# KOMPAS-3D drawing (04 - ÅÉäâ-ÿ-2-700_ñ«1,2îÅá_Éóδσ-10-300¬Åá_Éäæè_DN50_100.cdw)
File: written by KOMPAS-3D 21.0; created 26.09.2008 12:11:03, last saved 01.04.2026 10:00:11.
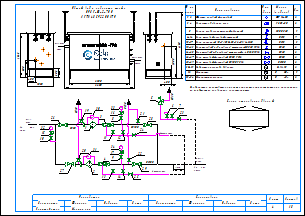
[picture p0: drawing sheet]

Sheets 1-2: A3, landscape

Document properties: Наименование: Макро:21; Автор: RaskoAdmin; Форматы листов документа: 2xA3; Полное имя файла: \\UR38nt01\Departments\КТО\КБ ПУРДГ\Заявки\Прайс-лист на типовые шкафы ГРПШ\ПРДГ_стандарт_20_03_2026\ПРДГ с РДСК\ПРДГ-Ш-2-700_до1,2МПа_Рвых-10-300кПа_РДСК_DN50_100.cdw

Title block, sheet 1: Наименование: Пункт учета газа / ПУГ-Ш-400-Р / ЛГТИ.485922.001ТУ; designation: ЛГТИ.03.4411141; sheet number: 1; Количество листов документа: 2; organisation: ООО "ЭЛЬСТЕР Газэлектроника"; Форматы листов документа: A3; stored path: C:\Рабочие документы\Компас\ПУГ\Схема.cdw; Разработал: Устинов; Проверил: Кошкин; Утвердил: Кошкин
Title block, sheet 2: sheet number: 2; stored path: D:\Рабочие документы\Заявки\ПУРДГ\ПУРДГ-ШУЭО-2-100-Р 4411220.cdw; designation, second copy: ЛГТИ.03.4411141-

Views: Вид 1, Вид 2
Referenced files: wcvoit.frw
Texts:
  Normal
  Вход
  газа
  PDI
  Выход
  Р=     кПа
  DN100
  DN50
  DN20
  Импульс DN20
  ≥5DN
  HYSWLongFangSong
  № на
  схеме
  Усл.
  обозн.
  Марка
  (модель)
  Кол.
  Фильтр газовый фланцевый
  ФГ 16-50
  Регулятор давления газа
  РДCК-50
  Клапан предохранительный сбросной
  КПС DN20
  Кран шаровой газовый латунный
  DN15
  Кран кнопочный VE-РАСКО-НЗ-1,6-G1/2-М20
  Кран шаровой "под приварку" штуцерный DN20 PN16
  Кран шаровой "под приварку" штуцерный п/п DN20 PN16
  Кран шаровой фланцевый DN50 PN16
  Кран шаровой фланцевый DN100 PN16
  Индикатор перепада давления
  Delta 15
  Манометр
  Манометр-напоромер
  0...     МПа
  0...     кПа
  Общий вид и габариты шкафа
  ПРДГ-Ш-2-700
  Выход газа
  Вход газа
  Схема открывания дверей
  Р=        МПа
  logo-rasko-ge.png
  Предприятие изготовитель может заменять комплектующие на аналогичные,
  не ухудшающие заявленных характеристик.
  Должность
  Конструктор
  Фамилия
  Подпись
  Дата
  Согласовано
  Максимкин
  Лист
  Листов
  POLYLINE_STYLE_0.18_RGB_0_0_0
  POLYLINE_STYLE_0.50_RGB_0_0_0
  POLYLINE_STYLE_0.34_RGB_0_0_0
  PHANTOM_RGB_0_0_0_SC_1_THICK_0.18
  K5LT_THIN_RGB_0_0_0_THICK_0.18
  K5LT32769_RGB_0_0_0_THICK_0.18
  K5LT12_RGB_0_0_0_SC_1_THICK_0.18
  K5LT_DASHED_RGB_0_0_0_SC_1_THICK_0.18
  ACISOTGL_RGB_0_0_0_SC_0.8_THICK_0.25
  CONTINUOUS_RGB_0_127_31_THICK_0.3
  CONTINUOUS_RGB_0_0_255_THICK_0.35
  CONTINUOUS_RGB_255_0_0_THICK_0.35
  POLYLINE_STYLE_0.25_RGB_0_0_0
  CONTINUOUS_RGB_0_0_0_THICK_0.5
  POLYLINE_STYLE_0.35_RGB_0_0_255
  CONTINUOUS_RGB_0_0_0_THICK_0.4
  CONTINUOUS_RGB_0_0_0_THICK_0.35
  Без оформления
Dimensions and other numbers on the sheet: 1; 2; 3; 4; 5; 10; 27; 28; 29; 23; 8; 12; 19; 20; 21; 22; 25; 24; 30; 31; 15; 16; 26; 6; 7; 11; 14; 13; 33; 1, 2; 3, 4; 6-14; 9; 15-17; 18-23; 24-25; 26-27; 28-29; 30-31; 32; 33-34; 400; 1050; 500; 305; 2300; 1565; 2600; 17; 34; 1000; 4130; 18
